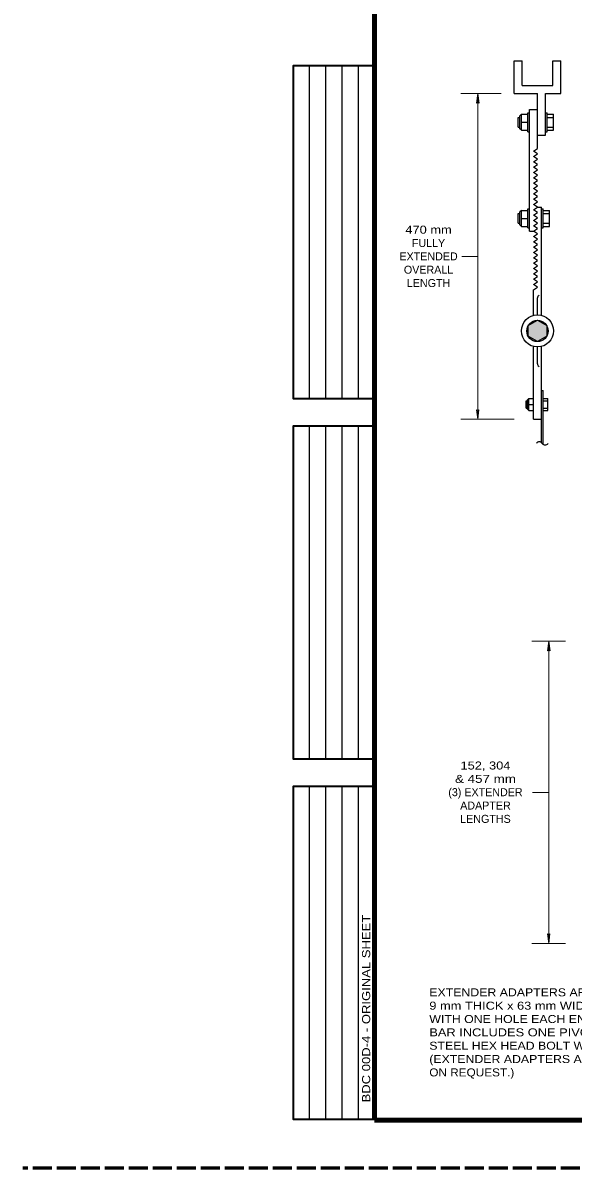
# Model space of a CAD drawing. Extents: x 312583 to 312853, y 144376 to 144586.
# Drawn here: x 312583.5 to 312635.1, y 144418.6 to 144525.9 of the extents above; entities that cross this region are included whole.
import ezdxf
from ezdxf.enums import TextEntityAlignment as Align

# ---------------------------------------------------------------- set-up
doc = ezdxf.new("R2010")
doc.units = 0
doc.header["$LTSCALE"] = 0.3
doc.linetypes.add('LONG_DASHED', pattern=[7.5, 6, -1.5])
for name, color, linetype, lineweight in [('1', 7, 'Continuous', 25), ('2', 7, 'Continuous', 13), ('63', 7, 'LONG_DASHED', 60)]:
    doc.layers.add(name, color=color, linetype=linetype, lineweight=lineweight)

msp = doc.modelspace()

# ---------------------------------------------------------------- hatches: boundary and pattern name
at = {"layer": '1'}
for points in [[(312632.7647, 144497.0181, 1), (312630.7647, 144497.0181, 1)], [(312631.7647, 144498.0181), (312632.6307, 144497.5181), (312632.6307, 144496.5181), (312631.7647, 144496.0181), (312630.8986, 144496.5181), (312630.8986, 144497.5181)]]:
    msp.add_hatch(color=256, dxfattribs=at).paths.add_polyline_path(points)

# ---------------------------------------------------------------- linework, layer by layer
for p, q in [((312610.4087, 144490.6573), (312610.4087, 144521.8756)), ((312611.9315, 144490.6573), (312611.9315, 144521.8756)), ((312613.4543, 144490.6573), (312613.4543, 144521.8756)), ((312614.9772, 144490.6573), (312614.9772, 144521.8756)), ((312629.5897, 144519.2653), (312629.5897, 144522.3287)), ((312629.5897, 144522.3287), (312630.3397, 144522.3287)), ((312630.3397, 144520.0153), (312630.3397, 144522.3287)), ((312633.1897, 144520.0153), (312633.1897, 144522.3287)), ((312633.1897, 144522.3287), (312633.9397, 144522.3287)), ((312633.9397, 144519.2653), (312633.9397, 144522.3287)), ((312630.3397, 144520.0153), (312633.1897, 144520.0153)), ((312629.5897, 144519.2653), (312631.7647, 144519.2653)), ((312632.5147, 144519.2653), (312633.9397, 144519.2653)), ((312631.0147, 144517.7653), (312631.7647, 144517.7653)), ((312631.0147, 144506.3653), (312631.0147, 144517.7653)), ((312629.9647, 144516.1153), (312629.9647, 144517.0153)), ((312629.9647, 144517.0153), (312630.1147, 144517.0153)), ((312630.2647, 144517.3153), (312630.1147, 144517.1653)), ((312630.1147, 144515.9653), (312630.1147, 144517.1653)), ((312630.2647, 144515.8153), (312630.2647, 144517.3153)), ((312630.2647, 144517.3153), (312630.8647, 144517.3153)), ((312630.2647, 144516.5653), (312630.8647, 144516.5653)), ((312632.5147, 144517.4653), (312632.6647, 144517.4653)), ((312632.6647, 144515.6653), (312632.6647, 144517.4653)), ((312632.6647, 144517.3153), (312633.2647, 144517.3153)), ((312632.6647, 144517.0153), (312633.2647, 144517.0153)), ((312633.2647, 144515.8153), (312633.2647, 144517.3153)), ((312629.9647, 144516.1153), (312630.1147, 144516.1153)), ((312630.2647, 144515.8153), (312630.1147, 144515.9653)), ((312630.2647, 144515.8153), (312630.8647, 144515.8153)), ((312630.8647, 144515.6653), (312631.0147, 144515.6653)), ((312632.5147, 144515.6653), (312632.6647, 144515.6653)), ((312632.6647, 144516.1153), (312633.2647, 144516.1153)), ((312632.6647, 144515.8153), (312633.2647, 144515.8153)), ((312629.9647, 144507.1153), (312629.9647, 144508.0153)), ((312629.9647, 144508.0153), (312630.1147, 144508.0153)), ((312630.2647, 144508.3153), (312630.1147, 144508.1653)), ((312630.1147, 144506.9653), (312630.1147, 144508.1653)), ((312630.2647, 144506.8153), (312630.2647, 144508.3153)), ((312630.2647, 144508.3153), (312630.8647, 144508.3153)), ((312631.7647, 144508.6153), (312632.1397, 144508.6153)), ((312632.1397, 144498.4704), (312632.1397, 144508.6153)), ((312632.1397, 144508.4653), (312632.2897, 144508.4653)), ((312632.2897, 144506.6653), (312632.2897, 144508.4653)), ((312632.2897, 144508.3153), (312632.8897, 144508.3153)), ((312632.2897, 144508.0153), (312632.8897, 144508.0153)), ((312632.8897, 144506.8153), (312632.8897, 144508.3153)), ((312629.9647, 144507.1153), (312630.1147, 144507.1153)), ((312630.2647, 144506.8153), (312630.1147, 144506.9653)), ((312630.2647, 144507.5653), (312630.8647, 144507.5653)), ((312632.2897, 144507.1153), (312632.8897, 144507.1153)), ((312630.2647, 144506.8153), (312630.8647, 144506.8153)), ((312630.8647, 144506.6653), (312631.0147, 144506.6653)), ((312631.0147, 144506.3653), (312631.3897, 144506.3653)), ((312632.1397, 144506.6653), (312632.2897, 144506.6653)), ((312632.2897, 144506.8153), (312632.8897, 144506.8153)), ((312631.3897, 144498.4704), (312631.3897, 144500.8653)), ((312631.7647, 144498.5181), (312631.7647, 144500.106)), ((312631.3897, 144488.7385), (312631.3897, 144495.5657)), ((312631.7647, 144493.9302), (312631.7647, 144495.5181)), ((312632.1397, 144486.5533), (312632.1397, 144495.5657)), ((312632.1397, 144491.4385), (312632.2897, 144491.4385)), ((312632.2897, 144486.3994), (312632.2897, 144491.4385)), ((312630.7147, 144489.7885), (312630.7147, 144490.4635)), ((312630.7147, 144490.4635), (312630.8272, 144490.4635)), ((312630.7147, 144489.7885), (312630.8272, 144489.7885)), ((312630.9397, 144490.6885), (312630.8272, 144490.576)), ((312630.8272, 144489.676), (312630.8272, 144490.576)), ((312630.9397, 144489.5635), (312630.8272, 144489.676)), ((312630.9397, 144489.5635), (312630.9397, 144490.6885)), ((312630.9397, 144490.6885), (312631.3897, 144490.6885)), ((312630.9397, 144490.126), (312631.3897, 144490.126)), ((312632.2897, 144490.6885), (312632.7397, 144490.6885)), ((312632.2897, 144490.4635), (312632.7397, 144490.4635)), ((312632.2897, 144489.7885), (312632.7397, 144489.7885)), ((312632.7397, 144489.5635), (312632.7397, 144490.6885)), ((312630.9397, 144489.5635), (312631.3897, 144489.5635)), ((312631.3897, 144488.7385), (312632.1397, 144488.7385)), ((312632.2897, 144489.5635), (312632.7397, 144489.5635)), ((312610.4087, 144456.901), (312610.4087, 144488.1192)), ((312611.9315, 144456.901), (312611.9315, 144488.1192)), ((312613.4543, 144456.901), (312613.4543, 144488.1192)), ((312614.9772, 144456.901), (312614.9772, 144488.1192)), ((312610.4087, 144423.1446), (312610.4087, 144454.3629)), ((312611.9315, 144423.1446), (312611.9315, 144454.3629)), ((312613.4543, 144423.1446), (312613.4543, 144454.3629)), ((312614.9772, 144423.1446), (312614.9772, 144454.3629))]:
    msp.add_line(p, q, dxfattribs=at)
at = {"layer": '1', "lineweight": 158}
msp.add_line((312616.5, 144423.0846), (312849, 144423.0846), dxfattribs=at)
msp.add_lwpolyline([(312616.5, 144423.1446), (312616.5, 144585.0846), (312849, 144585.0846)], dxfattribs=at)
at = {"layer": '1', "lineweight": 35}
for points in [[(312616.5, 144490.6573), (312608.8858, 144490.6573), (312608.8858, 144521.8756), (312616.5, 144521.8756)], [(312616.5, 144456.901), (312608.8858, 144456.901), (312608.8858, 144488.1192), (312616.5, 144488.1192)], [(312616.5, 144423.1446), (312608.8858, 144423.1446), (312608.8858, 144454.3629), (312616.5, 144454.3629)]]:
    msp.add_lwpolyline(points, dxfattribs=at)
at = {"layer": '1'}
for points in [[(312631.3897, 144506.3653), (312631.7647, 144506.6153), (312631.3897, 144506.8653), (312631.7647, 144507.1153), (312631.3897, 144507.3653), (312631.7647, 144507.6153), (312631.3897, 144507.8653), (312631.7647, 144508.1153), (312631.3897, 144508.3653), (312631.7647, 144508.6153), (312631.3897, 144508.8653), (312631.7647, 144509.1153), (312631.3897, 144509.3653), (312631.7647, 144509.6153), (312631.3897, 144509.8653), (312631.7647, 144510.1153), (312631.3897, 144510.3653), (312631.7647, 144510.6153), (312631.3897, 144510.8653), (312631.7647, 144511.1153), (312631.3897, 144511.3653), (312631.7647, 144511.6153), (312631.3897, 144511.8653), (312631.7647, 144512.1153), (312631.3897, 144512.3653), (312631.7647, 144512.6153), (312631.3897, 144512.8653), (312631.7647, 144513.1153), (312631.3897, 144513.3653), (312631.7647, 144513.6153), (312631.3897, 144513.8653), (312631.7647, 144514.1153), (312631.7647, 144519.2653)], [(312631.7647, 144515.3653), (312632.5147, 144515.3653), (312632.5147, 144519.2653)], [(312630.8647, 144515.6653), (312630.8647, 144517.4653), (312631.0147, 144517.4653)], [(312630.8647, 144506.6653), (312630.8647, 144508.4653), (312631.0147, 144508.4653)], [(312631.3897, 144500.8653), (312631.7647, 144501.1153), (312631.3897, 144501.3653), (312631.7647, 144501.6153), (312631.3897, 144501.8653), (312631.7647, 144502.1153), (312631.3897, 144502.3653), (312631.7647, 144502.6153), (312631.3897, 144502.8653), (312631.7647, 144503.1153), (312631.3897, 144503.3653), (312631.7647, 144503.6153), (312631.3897, 144503.8653), (312631.7647, 144504.1153), (312631.3897, 144504.3653), (312631.7647, 144504.6153), (312631.3897, 144504.8653), (312631.7647, 144505.1153), (312631.3897, 144505.3653), (312631.7647, 144505.6153), (312631.3897, 144505.8653), (312631.7647, 144506.1153), (312631.3897, 144506.3653), (312631.7647, 144506.6153), (312631.3897, 144506.8653), (312631.7647, 144507.1153), (312631.3897, 144507.3653), (312631.7647, 144507.6153), (312631.3897, 144507.8653), (312631.7647, 144508.1153), (312631.3897, 144508.3653), (312631.7647, 144508.6153)]]:
    msp.add_lwpolyline(points, dxfattribs=at)
msp.add_lwpolyline([(312631.7647, 144498.0181), (312632.6307, 144497.5181), (312632.6307, 144496.5181), (312631.7647, 144496.0181), (312630.8986, 144496.5181), (312630.8986, 144497.5181)], close=True, dxfattribs=at)
for radius in [1.5, 1]:
    msp.add_circle((312631.7647, 144497.0181), radius, dxfattribs=at)
for centre, radius, start, end in [((312631.9324, 144486.2926), 0.3323, 33.87567, 144.14149), ((312632.4822, 144486.6802), 0.3405, 216.4613, 322.83048)]:
    msp.add_arc(centre, radius, start, end, dxfattribs=at)
for centre, major_axis, start_param, end_param in [((312632.1983, 144500.1457), (0.4336, 0.0397), 2.23856303, 3.14150897), ((312632.1983, 144493.8905), (0.4336, -0.0397), 3.14167633, 4.04462228)]:
    msp.add_ellipse(centre, major_axis=major_axis, ratio=0.649846, start_param=start_param, end_param=end_param, dxfattribs=at)
at = {"layer": '2'}
for p, q in [((312624.5897, 144519.2653), (312628.3646, 144519.2653)), ((312626.1685, 144519.2653), (312626.1685, 144488.7385)), ((312626.1685, 144504.0019), (312624.6586, 144504.0019)), ((312624.5897, 144488.7385), (312629.5945, 144488.7385)), ((312631.2437, 144467.951), (312634.4012, 144467.951)), ((312632.8225, 144467.951), (312632.8225, 144439.6177)), ((312632.8225, 144453.7844), (312631.3126, 144453.7844)), ((312631.2437, 144439.6177), (312634.4012, 144439.6177))]:
    msp.add_line(p, q, dxfattribs=at)
for points in [[(312626.0585, 144518.3653), (312626.1685, 144519.2653), (312626.2885, 144518.3653), (312626.1685, 144518.4553)], [(312626.2785, 144489.6385), (312626.1685, 144488.7385), (312626.0485, 144489.6385), (312626.1685, 144489.5485)], [(312632.7125, 144467.051), (312632.8225, 144467.951), (312632.9425, 144467.051), (312632.8225, 144467.141)], [(312632.9325, 144440.5177), (312632.8225, 144439.6177), (312632.7025, 144440.5177), (312632.8225, 144440.4277)]]:
    msp.add_lwpolyline(points, close=True, dxfattribs=at)
at = {"layer": '63'}
msp.add_line((312851.75, 144418.5846), (312583.526, 144418.5846), dxfattribs=at)

# ---------------------------------------------------------------- texts
at = {"layer": '1', "width": 1.2}
msp.add_text('BDC 00D-4 - ORIGINAL SHEET', height=0.7614, rotation=90, dxfattribs=at).set_placement((312616.0832, 144424.7374))
at = {"layer": '2'}
for s, width, p in [('470 mm', 1.2, (312621.5544, 144506.1304)), ('152, 304', 1.2, (312626.8887, 144455.9284)), ('& 457 mm', 1.25, (312626.8887, 144454.6784))]:
    msp.add_text(s, height=0.75, dxfattribs=dict(at, width=width)).set_placement(p, align=Align.CENTER)
for s, p in [('FULLY', (312621.5544, 144504.8804)), ('EXTENDED', (312621.5545, 144503.6304)), ('OVERALL', (312621.5544, 144502.3804)), ('LENGTH', (312621.5545, 144501.1304)), ('(3) EXTENDER', (312626.8887, 144453.4284)), ('ADAPTER', (312626.8887, 144452.1784)), ('LENGTHS', (312626.8887, 144450.9284))]:
    msp.add_text(s, height=0.75, dxfattribs=at).set_placement(p, align=Align.CENTER)
for s, width, p in [('EXTENDER ADAPTERS ARE ALL ALUMINUM 6061T6 ALLOY.', 1.15, (312621.6238, 144434.6762)), ('9 mm THICK x 63 mm WIDE BAR x VARIABLE LENGTH COMPLETE', 1.2, (312621.6238, 144433.4262)), ('WITH ONE HOLE EACH END FOR 13 mm BOLT. EACH EXTENDER', 1.15, (312621.6238, 144432.1762)), ('BAR INCLUDES ONE PIVOT POINT M12 x 40 mm STAINLESS', 1.2, (312621.6238, 144430.9262)), ('STEEL HEX HEAD BOLT WITH HEX LOCK NUT AND 2 WASHERS.', 1.15, (312621.6238, 144429.6762)), ('(EXTENDER ADAPTERS ARE AVAILABLE IN VARIABLE LENGTHS', 1.15, (312621.6238, 144428.4262)), ('ON REQUEST.)', 1.1, (312621.6238, 144427.1762))]:
    msp.add_text(s, height=0.75, dxfattribs=dict(at, width=width)).set_placement(p)

doc.saveas('drawing.dxf')
